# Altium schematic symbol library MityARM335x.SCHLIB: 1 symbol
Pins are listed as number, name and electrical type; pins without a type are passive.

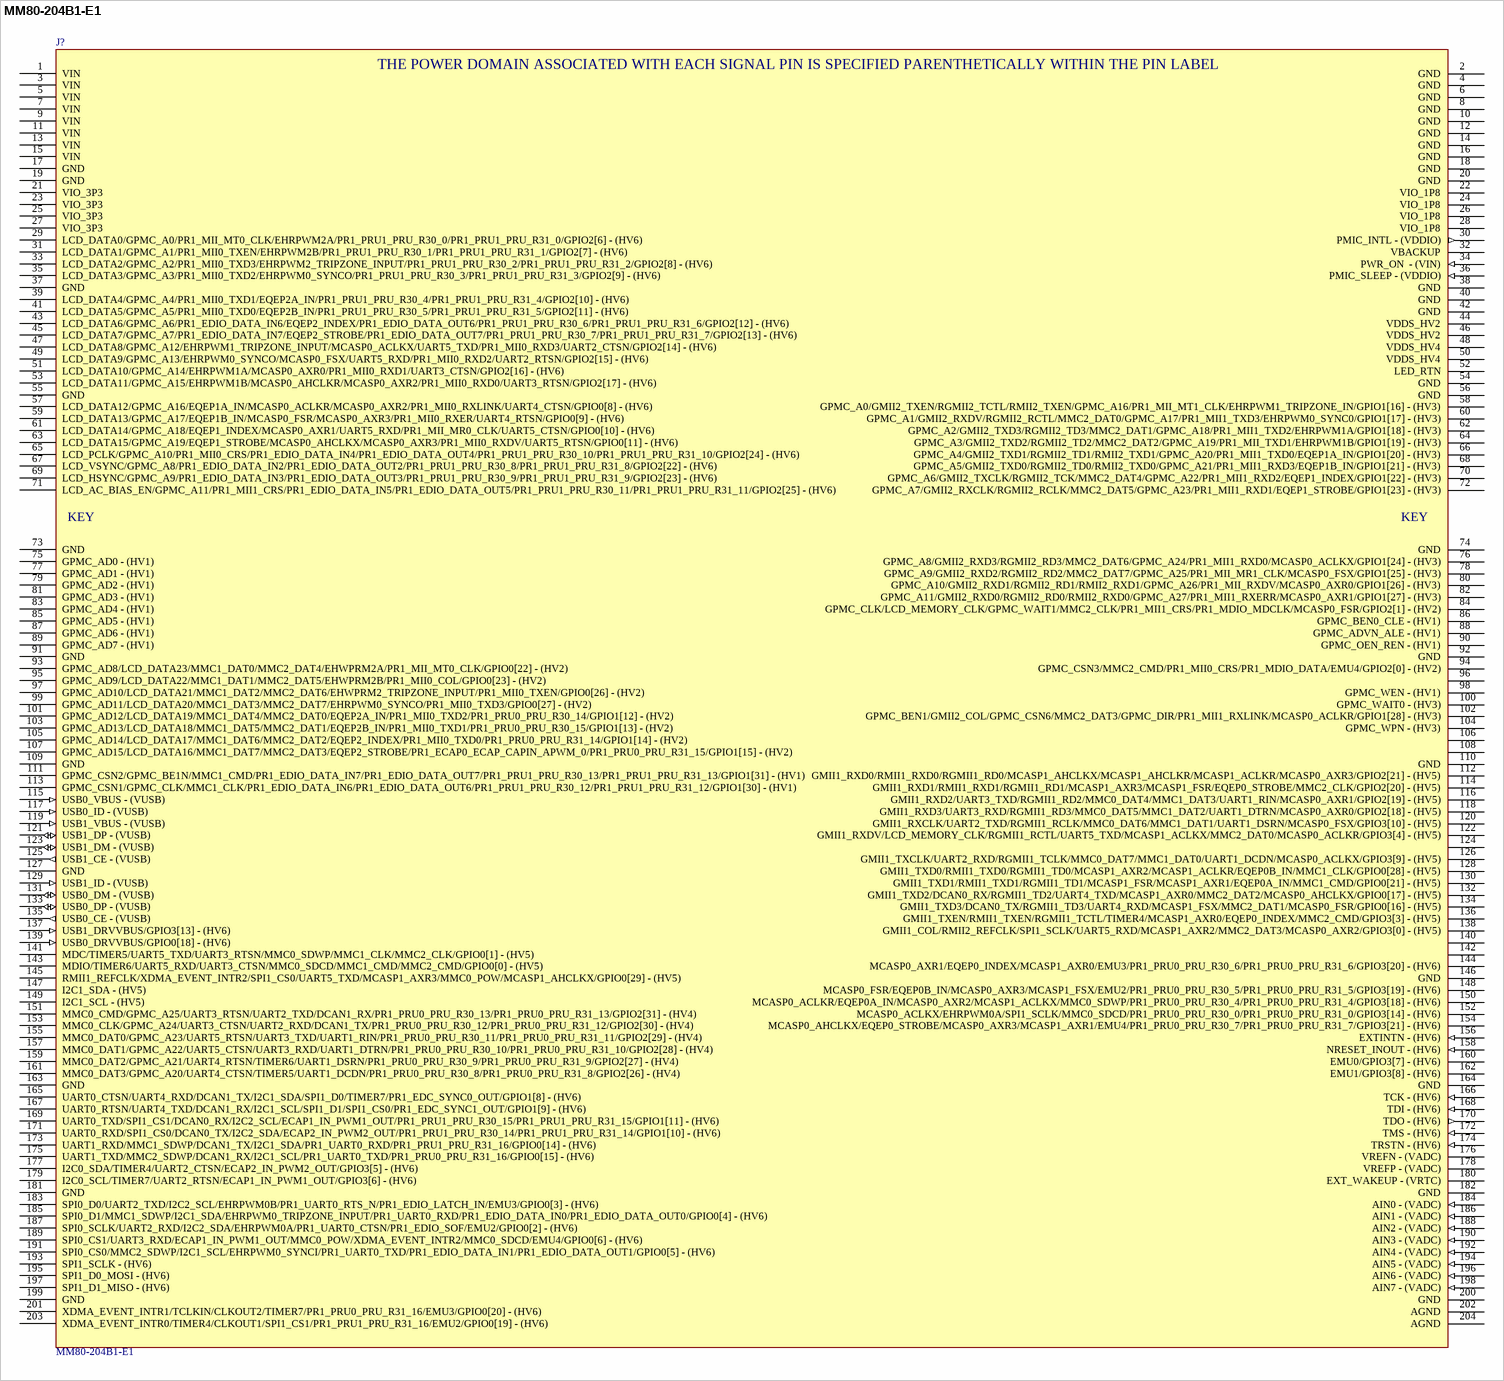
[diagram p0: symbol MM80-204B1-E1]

## MM80-204B1-E1
designator J?
Board-edge component for DDR3 sockets, customized for MityARM-335x; Mfg: JAE; User: Alexei
footprint DDR2_EDGE
footprint MM80-204B1-E1 (CONN SODIMM DDR3 204POS R/A SMD)
pins: 1 VIN, 2 GND, 3 VIN, 4 GND, 5 VIN, 6 GND, 7 VIN, 8 GND, 9 VIN, 10 GND, 11 VIN, 12 GND, 13 VIN, 14 GND, 15 VIN, 16 GND, 17 GND, 18 GND, 19 GND, 20 GND, 21 VIO_3P3, 22 VIO_1P8 (power), 23 VIO_3P3, 24 VIO_1P8 (power), 25 VIO_3P3, 26 VIO_1P8 (power), 27 VIO_3P3, 28 VIO_1P8 (power), 29 LCD_DATA0/GPMC_A0/PR1_MII_MT0_CLK/EHRPWM2A/PR1_PRU1_PRU_R30_0/PR1_PRU1_PRU_R31_0/GPIO2[6] - (HV6), 30 PMIC_INTL - (VDDIO) (out), 31 LCD_DATA1/GPMC_A1/PR1_MII0_TXEN/EHRPWM2B/PR1_PRU1_PRU_R30_1/PR1_PRU1_PRU_R31_1/GPIO2[7] - (HV6), 32 VBACKUP, 33 LCD_DATA2/GPMC_A2/PR1_MII0_TXD3/EHRPWM2_TRIPZONE_INPUT/PR1_PRU1_PRU_R30_2/PR1_PRU1_PRU_R31_2/GPIO2[8] - (HV6), 34 PWR_ON  - (VIN) (in), 35 LCD_DATA3/GPMC_A3/PR1_MII0_TXD2/EHRPWM0_SYNCO/PR1_PRU1_PRU_R30_3/PR1_PRU1_PRU_R31_3/GPIO2[9] - (HV6), 36 PMIC_SLEEP - (VDDIO) (in), 37 GND, 38 GND, 39 LCD_DATA4/GPMC_A4/PR1_MII0_TXD1/EQEP2A_IN/PR1_PRU1_PRU_R30_4/PR1_PRU1_PRU_R31_4/GPIO2[10] - (HV6), 40 GND, 41 LCD_DATA5/GPMC_A5/PR1_MII0_TXD0/EQEP2B_IN/PR1_PRU1_PRU_R30_5/PR1_PRU1_PRU_R31_5/GPIO2[11] - (HV6), 42 GND, 43 LCD_DATA6/GPMC_A6/PR1_EDIO_DATA_IN6/EQEP2_INDEX/PR1_EDIO_DATA_OUT6/PR1_PRU1_PRU_R30_6/PR1_PRU1_PRU_R31_6/GPIO2[12] - (HV6), 44 VDDS_HV2 (power), 45 LCD_DATA7/GPMC_A7/PR1_EDIO_DATA_IN7/EQEP2_STROBE/PR1_EDIO_DATA_OUT7/PR1_PRU1_PRU_R30_7/PR1_PRU1_PRU_R31_7/GPIO2[13] - (HV6), 46 VDDS_HV2 (power), 47 LCD_DATA8/GPMC_A12/EHRPWM1_TRIPZONE_INPUT/MCASP0_ACLKX/UART5_TXD/PR1_MII0_RXD3/UART2_CTSN/GPIO2[14] - (HV6), 48 VDDS_HV4 (power), 49 LCD_DATA9/GPMC_A13/EHRPWM0_SYNCO/MCASP0_FSX/UART5_RXD/PR1_MII0_RXD2/UART2_RTSN/GPIO2[15] - (HV6), 50 VDDS_HV4 (power), 51 LCD_DATA10/GPMC_A14/EHRPWM1A/MCASP0_AXR0/PR1_MII0_RXD1/UART3_CTSN/GPIO2[16] - (HV6), 52 LED_RTN, 53 LCD_DATA11/GPMC_A15/EHRPWM1B/MCASP0_AHCLKR/MCASP0_AXR2/PR1_MII0_RXD0/UART3_RTSN/GPIO2[17] - (HV6), 54 GND, 55 GND, 56 GND, 57 LCD_DATA12/GPMC_A16/EQEP1A_IN/MCASP0_ACLKR/MCASP0_AXR2/PR1_MII0_RXLINK/UART4_CTSN/GPIO0[8] - (HV6), 58 GPMC_A0/GMII2_TXEN/RGMII2_TCTL/RMII2_TXEN/GPMC_A16/PR1_MII_MT1_CLK/EHRPWM1_TRIPZONE_IN/GPIO1[16] - (HV3), 59 LCD_DATA13/GPMC_A17/EQEP1B_IN/MCASP0_FSR/MCASP0_AXR3/PR1_MII0_RXER/UART4_RTSN/GPIO0[9] - (HV6), 60 GPMC_A1/GMII2_RXDV/RGMII2_RCTL/MMC2_DAT0/GPMC_A17/PR1_MII1_TXD3/EHRPWM0_SYNC0/GPIO1[17] - (HV3), 61 LCD_DATA14/GPMC_A18/EQEP1_INDEX/MCASP0_AXR1/UART5_RXD/PR1_MII_MR0_CLK/UART5_CTSN/GPIO0[10] - (HV6), 62 GPMC_A2/GMII2_TXD3/RGMII2_TD3/MMC2_DAT1/GPMC_A18/PR1_MII1_TXD2/EHRPWM1A/GPIO1[18] - (HV3), 63 LCD_DATA15/GPMC_A19/EQEP1_STROBE/MCASP0_AHCLKX/MCASP0_AXR3/PR1_MII0_RXDV/UART5_RTSN/GPIO0[11] - (HV6), 64 GPMC_A3/GMII2_TXD2/RGMII2_TD2/MMC2_DAT2/GPMC_A19/PR1_MII_TXD1/EHRPWM1B/GPIO1[19] - (HV3), 65 LCD_PCLK/GPMC_A10/PR1_MII0_CRS/PR1_EDIO_DATA_IN4/PR1_EDIO_DATA_OUT4/PR1_PRU1_PRU_R30_10/PR1_PRU1_PRU_R31_10/GPIO2[24] - (HV6), 66 GPMC_A4/GMII2_TXD1/RGMII2_TD1/RMII2_TXD1/GPMC_A20/PR1_MII1_TXD0/EQEP1A_IN/GPIO1[20] - (HV3), 67 LCD_VSYNC/GPMC_A8/PR1_EDIO_DATA_IN2/PR1_EDIO_DATA_OUT2/PR1_PRU1_PRU_R30_8/PR1_PRU1_PRU_R31_8/GPIO2[22] - (HV6), 68 GPMC_A5/GMII2_TXD0/RGMII2_TD0/RMII2_TXD0/GPMC_A21/PR1_MII1_RXD3/EQEP1B_IN/GPIO1[21] - (HV3), 69 LCD_HSYNC/GPMC_A9/PR1_EDIO_DATA_IN3/PR1_EDIO_DATA_OUT3/PR1_PRU1_PRU_R30_9/PR1_PRU1_PRU_R31_9/GPIO2[23] - (HV6), 70 GPMC_A6/GMII2_TXCLK/RGMII2_TCK/MMC2_DAT4/GPMC_A22/PR1_MII1_RXD2/EQEP1_INDEX/GPIO1[22] - (HV3), 71 LCD_AC_BIAS_EN/GPMC_A11/PR1_MII1_CRS/PR1_EDIO_DATA_IN5/PR1_EDIO_DATA_OUT5/PR1_PRU1_PRU_R30_11/PR1_PRU1_PRU_R31_11/GPIO2[25] - (HV6), 72 GPMC_A7/GMII2_RXCLK/RGMII2_RCLK/MMC2_DAT5/GPMC_A23/PR1_MII1_RXD1/EQEP1_STROBE/GPIO1[23] - (HV3), 73 GND, 74 GND, 75 GPMC_AD0 - (HV1), 76 GPMC_A8/GMII2_RXD3/RGMII2_RD3/MMC2_DAT6/GPMC_A24/PR1_MII1_RXD0/MCASP0_ACLKX/GPIO1[24] - (HV3), 77 GPMC_AD1 - (HV1), 78 GPMC_A9/GMII2_RXD2/RGMII2_RD2/MMC2_DAT7/GPMC_A25/PR1_MII_MR1_CLK/MCASP0_FSX/GPIO1[25] - (HV3), 79 GPMC_AD2 - (HV1), 80 GPMC_A10/GMII2_RXD1/RGMII2_RD1/RMII2_RXD1/GPMC_A26/PR1_MII_RXDV/MCASP0_AXR0/GPIO1[26] - (HV3), 81 GPMC_AD3 - (HV1), 82 GPMC_A11/GMII2_RXD0/RGMII2_RD0/RMII2_RXD0/GPMC_A27/PR1_MII1_RXERR/MCASP0_AXR1/GPIO1[27] - (HV3), 83 GPMC_AD4 - (HV1), 84 GPMC_CLK/LCD_MEMORY_CLK/GPMC_WAIT1/MMC2_CLK/PR1_MII1_CRS/PR1_MDIO_MDCLK/MCASP0_FSR/GPIO2[1] - (HV2), 85 GPMC_AD5 - (HV1), 86 GPMC_BEN0_CLE - (HV1), 87 GPMC_AD6 - (HV1), 88 GPMC_ADVN_ALE - (HV1), 89 GPMC_AD7 - (HV1), 90 GPMC_OEN_REN - (HV1), 91 GND, 92 GND, 93 GPMC_AD8/LCD_DATA23/MMC1_DAT0/MMC2_DAT4/EHWPRM2A/PR1_MII_MT0_CLK/GPIO0[22] - (HV2), 94 GPMC_CSN3/MMC2_CMD/PR1_MII0_CRS/PR1_MDIO_DATA/EMU4/GPIO2[0] - (HV2), 95 GPMC_AD9/LCD_DATA22/MMC1_DAT1/MMC2_DAT5/EHWPRM2B/PR1_MII0_COL/GPIO0[23] - (HV2), 96, 97 GPMC_AD10/LCD_DATA21/MMC1_DAT2/MMC2_DAT6/EHWPRM2_TRIPZONE_INPUT/PR1_MII0_TXEN/GPIO0[26] - (HV2), 98 GPMC_WEN - (HV1), 99 GPMC_AD11/LCD_DATA20/MMC1_DAT3/MMC2_DAT7/EHRPWM0_SYNCO/PR1_MII0_TXD3/GPIO0[27] - (HV2), 100 GPMC_WAIT0 - (HV3), 101 GPMC_AD12/LCD_DATA19/MMC1_DAT4/MMC2_DAT0/EQEP2A_IN/PR1_MII0_TXD2/PR1_PRU0_PRU_R30_14/GPIO1[12] - (HV2), 102 GPMC_BEN1/GMII2_COL/GPMC_CSN6/MMC2_DAT3/GPMC_DIR/PR1_MII1_RXLINK/MCASP0_ACLKR/GPIO1[28] - (HV3), 103 GPMC_AD13/LCD_DATA18/MMC1_DAT5/MMC2_DAT1/EQEP2B_IN/PR1_MII0_TXD1/PR1_PRU0_PRU_R30_15/GPIO1[13] - (HV2), 104 GPMC_WPN - (HV3), 105 GPMC_AD14/LCD_DATA17/MMC1_DAT6/MMC2_DAT2/EQEP2_INDEX/PR1_MII0_TXD0/PR1_PRU0_PRU_R31_14/GPIO1[14] - (HV2), 106, 107 GPMC_AD15/LCD_DATA16/MMC1_DAT7/MMC2_DAT3/EQEP2_STROBE/PR1_ECAP0_ECAP_CAPIN_APWM_0/PR1_PRU0_PRU_R31_15/GPIO1[15] - (HV2), 108, 109 GND, 110 GND, 111 GPMC_CSN2/GPMC_BE1N/MMC1_CMD/PR1_EDIO_DATA_IN7/PR1_EDIO_DATA_OUT7/PR1_PRU1_PRU_R30_13/PR1_PRU1_PRU_R31_13/GPIO1[31] - (HV1), 112 GMII1_RXD0/RMII1_RXD0/RGMII1_RD0/MCASP1_AHCLKX/MCASP1_AHCLKR/MCASP1_ACLKR/MCASP0_AXR3/GPIO2[21] - (HV5), 113 GPMC_CSN1/GPMC_CLK/MMC1_CLK/PR1_EDIO_DATA_IN6/PR1_EDIO_DATA_OUT6/PR1_PRU1_PRU_R30_12/PR1_PRU1_PRU_R31_12/GPIO1[30] - (HV1), 114 GMII1_RXD1/RMII1_RXD1/RGMII1_RD1/MCASP1_AXR3/MCASP1_FSR/EQEP0_STROBE/MMC2_CLK/GPIO2[20] - (HV5), 115 USB0_VBUS - (VUSB) (in), 116 GMII1_RXD2/UART3_TXD/RGMII1_RD2/MMC0_DAT4/MMC1_DAT3/UART1_RIN/MCASP0_AXR1/GPIO2[19] - (HV5), 117 USB0_ID - (VUSB) (in), 118 GMII1_RXD3/UART3_RXD/RGMII1_RD3/MMC0_DAT5/MMC1_DAT2/UART1_DTRN/MCASP0_AXR0/GPIO2[18] - (HV5), 119 USB1_VBUS - (VUSB) (in), 120 GMII1_RXCLK/UART2_TXD/RGMII1_RCLK/MMC0_DAT6/MMC1_DAT1/UART1_DSRN/MCASP0_FSX/GPIO3[10] - (HV5), 121 USB1_DP - (VUSB) (io), 122 GMII1_RXDV/LCD_MEMORY_CLK/RGMII1_RCTL/UART5_TXD/MCASP1_ACLKX/MMC2_DAT0/MCASP0_ACLKR/GPIO3[4] - (HV5), 123 USB1_DM - (VUSB) (io), 124, 125 USB1_CE - (VUSB) (out), 126 GMII1_TXCLK/UART2_RXD/RGMII1_TCLK/MMC0_DAT7/MMC1_DAT0/UART1_DCDN/MCASP0_ACLKX/GPIO3[9] - (HV5), 127 GND, 128 GMII1_TXD0/RMII1_TXD0/RGMII1_TD0/MCASP1_AXR2/MCASP1_ACLKR/EQEP0B_IN/MMC1_CLK/GPIO0[28] - (HV5), 129 USB1_ID - (VUSB) (in), 130 GMII1_TXD1/RMII1_TXD1/RGMII1_TD1/MCASP1_FSR/MCASP1_AXR1/EQEP0A_IN/MMC1_CMD/GPIO0[21] - (HV5), 131 USB0_DM - (VUSB) (io), 132 GMII1_TXD2/DCAN0_RX/RGMII1_TD2/UART4_TXD/MCASP1_AXR0/MMC2_DAT2/MCASP0_AHCLKX/GPIO0[17] - (HV5), 133 USB0_DP - (VUSB) (io), 134 GMII1_TXD3/DCAN0_TX/RGMII1_TD3/UART4_RXD/MCASP1_FSX/MMC2_DAT1/MCASP0_FSR/GPIO0[16] - (HV5), 135 USB0_CE - (VUSB) (out), 136 GMII1_TXEN/RMII1_TXEN/RGMII1_TCTL/TIMER4/MCASP1_AXR0/EQEP0_INDEX/MMC2_CMD/GPIO3[3] - (HV5), 137 USB1_DRVVBUS/GPIO3[13] - (HV6) (in), 138 GMII1_COL/RMII2_REFCLK/SPI1_SCLK/UART5_RXD/MCASP1_AXR2/MMC2_DAT3/MCASP0_AXR2/GPIO3[0] - (HV5), 139 USB0_DRVVBUS/GPIO0[18] - (HV6) (in), 140, 141 MDC/TIMER5/UART5_TXD/UART3_RTSN/MMC0_SDWP/MMC1_CLK/MMC2_CLK/GPIO0[1] - (HV5), 142, 143 MDIO/TIMER6/UART5_RXD/UART3_CTSN/MMC0_SDCD/MMC1_CMD/MMC2_CMD/GPIO0[0] - (HV5), 144 MCASP0_AXR1/EQEP0_INDEX/MCASP1_AXR0/EMU3/PR1_PRU0_PRU_R30_6/PR1_PRU0_PRU_R31_6/GPIO3[20] - (HV6), 145 RMII1_REFCLK/XDMA_EVENT_INTR2/SPI1_CS0/UART5_TXD/MCASP1_AXR3/MMC0_POW/MCASP1_AHCLKX/GPIO0[29] - (HV5), 146 GND, 147 I2C1_SDA - (HV5), 148 MCASP0_FSR/EQEP0B_IN/MCASP0_AXR3/MCASP1_FSX/EMU2/PR1_PRU0_PRU_R30_5/PR1_PRU0_PRU_R31_5/GPIO3[19] - (HV6), 149 I2C1_SCL - (HV5), 150 MCASP0_ACLKR/EQEP0A_IN/MCASP0_AXR2/MCASP1_ACLKX/MMC0_SDWP/PR1_PRU0_PRU_R30_4/PR1_PRU0_PRU_R31_4/GPIO3[18] - (HV6), 151 MMC0_CMD/GPMC_A25/UART3_RTSN/UART2_TXD/DCAN1_RX/PR1_PRU0_PRU_R30_13/PR1_PRU0_PRU_R31_13/GPIO2[31] - (HV4), 152 MCASP0_ACLKX/EHRPWM0A/SPI1_SCLK/MMC0_SDCD/PR1_PRU0_PRU_R30_0/PR1_PRU0_PRU_R31_0/GPIO3[14] - (HV6), 153 MMC0_CLK/GPMC_A24/UART3_CTSN/UART2_RXD/DCAN1_TX/PR1_PRU0_PRU_R30_12/PR1_PRU0_PRU_R31_12/GPIO2[30] - (HV4), 154 MCASP0_AHCLKX/EQEP0_STROBE/MCASP0_AXR3/MCASP1_AXR1/EMU4/PR1_PRU0_PRU_R30_7/PR1_PRU0_PRU_R31_7/GPIO3[21] - (HV6), 155 MMC0_DAT0/GPMC_A23/UART5_RTSN/UART3_TXD/UART1_RIN/PR1_PRU0_PRU_R30_11/PR1_PRU0_PRU_R31_11/GPIO2[29] - (HV4), 156 EXTINTN - (HV6) (in), 157 MMC0_DAT1/GPMC_A22/UART5_CTSN/UART3_RXD/UART1_DTRN/PR1_PRU0_PRU_R30_10/PR1_PRU0_PRU_R31_10/GPIO2[28] - (HV4), 158 NRESET_INOUT - (HV6) (in), 159 MMC0_DAT2/GPMC_A21/UART4_RTSN/TIMER6/UART1_DSRN/PR1_PRU0_PRU_R30_9/PR1_PRU0_PRU_R31_9/GPIO2[27] - (HV4), 160 EMU0/GPIO3[7] - (HV6), 161 MMC0_DAT3/GPMC_A20/UART4_CTSN/TIMER5/UART1_DCDN/PR1_PRU0_PRU_R30_8/PR1_PRU0_PRU_R31_8/GPIO2[26] - (HV4), 162 EMU1/GPIO3[8] - (HV6), 163 GND, 164 GND, 165 UART0_CTSN/UART4_RXD/DCAN1_TX/I2C1_SDA/SPI1_D0/TIMER7/PR1_EDC_SYNC0_OUT/GPIO1[8] - (HV6), 166 TCK - (HV6) (in), 167 UART0_RTSN/UART4_TXD/DCAN1_RX/I2C1_SCL/SPI1_D1/SPI1_CS0/PR1_EDC_SYNC1_OUT/GPIO1[9] - (HV6), 168 TDI - (HV6) (in), 169 UART0_TXD/SPI1_CS1/DCAN0_RX/I2C2_SCL/ECAP1_IN_PWM1_OUT/PR1_PRU1_PRU_R30_15/PR1_PRU1_PRU_R31_15/GPIO1[11] - (HV6), 170 TDO - (HV6) (out), 171 UART0_RXD/SPI1_CS0/DCAN0_TX/I2C2_SDA/ECAP2_IN_PWM2_OUT/PR1_PRU1_PRU_R30_14/PR1_PRU1_PRU_R31_14/GPIO1[10] - (HV6), 172 TMS - (HV6) (in), 173 UART1_RXD/MMC1_SDWP/DCAN1_TX/I2C1_SDA/PR1_UART0_RXD/PR1_PRU1_PRU_R31_16/GPIO0[14] - (HV6), 174 TRSTN - (HV6) (in), 175 UART1_TXD/MMC2_SDWP/DCAN1_RX/I2C1_SCL/PR1_UART0_TXD/PR1_PRU0_PRU_R31_16/GPIO0[15] - (HV6), 176 VREFN - (VADC) (power), 177 I2C0_SDA/TIMER4/UART2_CTSN/ECAP2_IN_PWM2_OUT/GPIO3[5] - (HV6), 178 VREFP - (VADC) (power), 179 I2C0_SCL/TIMER7/UART2_RTSN/ECAP1_IN_PWM1_OUT/GPIO3[6] - (HV6), 180 EXT_WAKEUP - (VRTC) (power), 181 GND, 182 GND, 183 SPI0_D0/UART2_TXD/I2C2_SCL/EHRPWM0B/PR1_UART0_RTS_N/PR1_EDIO_LATCH_IN/EMU3/GPIO0[3] - (HV6), 184 AIN0 - (VADC) (in), 185 SPI0_D1/MMC1_SDWP/I2C1_SDA/EHRPWM0_TRIPZONE_INPUT/PR1_UART0_RXD/PR1_EDIO_DATA_IN0/PR1_EDIO_DATA_OUT0/GPIO0[4] - (HV6), 186 AIN1 - (VADC) (in), 187 SPI0_SCLK/UART2_RXD/I2C2_SDA/EHRPWM0A/PR1_UART0_CTSN/PR1_EDIO_SOF/EMU2/GPIO0[2] - (HV6), 188 AIN2 - (VADC) (in), 189 SPI0_CS1/UART3_RXD/ECAP1_IN_PWM1_OUT/MMC0_POW/XDMA_EVENT_INTR2/MMC0_SDCD/EMU4/GPIO0[6] - (HV6), 190 AIN3 - (VADC) (in), 191 SPI0_CS0/MMC2_SDWP/I2C1_SCL/EHRPWM0_SYNCI/PR1_UART0_TXD/PR1_EDIO_DATA_IN1/PR1_EDIO_DATA_OUT1/GPIO0[5] - (HV6), 192 AIN4 - (VADC) (in), 193 SPI1_SCLK - (HV6), 194 AIN5 - (VADC) (in), 195 SPI1_D0_MOSI - (HV6), 196 AIN6 - (VADC) (in), 197 SPI1_D1_MISO - (HV6), 198 AIN7 - (VADC) (in), 199 GND, 200 GND, 201 XDMA_EVENT_INTR1/TCLKIN/CLKOUT2/TIMER7/PR1_PRU0_PRU_R31_16/EMU3/GPIO0[20] - (HV6), 202 AGND, 203 XDMA_EVENT_INTR0/TIMER4/CLKOUT1/SPI1_CS1/PR1_PRU1_PRU_R31_16/EMU2/GPIO0[19] - (HV6), 204 AGND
